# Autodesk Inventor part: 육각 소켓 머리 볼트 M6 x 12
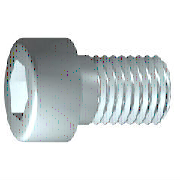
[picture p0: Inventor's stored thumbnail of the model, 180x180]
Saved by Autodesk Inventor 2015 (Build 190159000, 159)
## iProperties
IsCustomPart: 1
Created: 2012-02
Part Number: 육각 소켓 머리 볼트 M6 x 12
Material: 강철, 연강
Description: 원통형 머리 캡 나사
Document SubType Name: Modeling
Standard: JIS B 1176
Designer: mdu-01
Standards Organization: JIS
Language: ko-KR
Size Designation: M6 x 12
Categories: <MemberInstance><Categories><Category DisplayName="조임쇠" InternalName="e4da775c-781d-43d5-af7c-5136215cf5a6" Mnemonic="FSTN"><Category DisplayName="볼트" InternalN
Density: 1 g/cm^3
Appearance: 강철
Author: mdu-01
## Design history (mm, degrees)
sketch "스케치1"
  geometry: L1 (-1.333, 0)-(12, 0); L2 (12, 0)-(12, 3); L3 (12, 3)-(2.5, 3); L4 (2.5, 3)-(1.886, 3); L5 (1.886, 3)-(0, 3); L6 (0, 3)-(0, 5); L7 (0, 5)-(-6, 5); L8 (-6, 5)-(-6, 2.887); L9 (-6, 2.887)-(-3, 2.887); L10 (-3, 2.887)-(-1.333, 0); L11 (-9.6, 0)-(15.6, 0) reference; L12 (0, -1)-(0, 6) reference; L13 (2.5, 3)-(0, 3)
  constraints: 22 end point, 6 parallel, 2 collinear, 2 perpendicular, 1 horizontal, 1 point on line
  dimensions: "d1" = 9.5 distance from line of L3.end L2 (= GEL); "d2" = 0.61355 distance of L4.end L3.end (computed from GAL); "d3" = 6 distance between parallel lines of L8 L6 (= KOH); "d4" = 3 distance of L8.end L9.end (= INTI); "d5" = 60 deg angle of L10 L1; "d6" = 6 diameter of L3 L1 (= GD); "d7" = 6 diameter of L5 L1 (= BDM); "d8" = 5.7735 diameter of L9 L1 (= 1.1547 x SW); "d9" = 10 diameter of L7 L1 (= KOD); "d26" = 12 distance between parallel lines of L12 L2 (= NLG)
revolve "본체" sketch "스케치1" stored, may be unused: angle "d10" = 90 deg
sketch "스케치2"
  geometry: L1 (0, -7)-(0, 7) reference; L2 (-7, 0)-(7, 0) reference; L3 (2.887, 0)-(1.443, -2.5); L4 (1.443, -2.5)-(-1.443, -2.5); L5 (-1.443, -2.5)-(-2.887, 0); L6 (-2.887, 0)-(-1.443, 2.5); L7 (-1.443, 2.5)-(1.443, 2.5); L8 (1.443, 2.5)-(2.887, 0); 2 further points
  constraints: 12 end point, 1 coincident, 1 horizontal alignment, 1 point on line, 12 other
extrude "슬롯" join sketch "스케치2" stored distance "d11" = 10; taper "d12" = 0 deg
workplane "Work Plane1"
fillet "Fillet2" dims "d30" = 0.1 (= R)
body "Solid1"
fillet "모깎기1" dims "d17" = 0.6 (= RR)
feature "스레드" dims "d13" = 9.5 (= GEL), "d14" = 0
chamfer "모따기1" distance "d15" = 0.61345 (= -0.5 x SPD + 0.5 x GD); stored, may be unused: second distance "d16" = 0.61345 (= GUL), angle "d27" = 45 deg
other parameters: "GD" = 6 (= NND) [user parameter; used in 2 equation terms], "NLG" = 12 [user parameter; used in 1 equation term], "GEL" = 9.5 [user parameter; used in 2 equation terms], "KOD" = 10 [user parameter; used in 1 equation term], "KOH" = 6 [user parameter; used in 1 equation term], "INTI" = 3 [user parameter; used in 1 equation term], "GAL" = 0.61345 (= 0.61345 x PTC) [user parameter; used in 1 equation term], "GUL" = 0.61345 (= 0.61345 x PTC) [user parameter; used in 1 equation term], "BDM" = 6 (= NND) [user parameter; used in 1 equation term], "SW" = 5 [user parameter; used in 2 equation terms], "RR" = 0.6 [user parameter; used in 1 equation term], "SPD" = 4.7731 (= NND - 1.2269 x PTC) [user parameter; used in 1 equation term], "d19" = 0, "d28" = 0, "d29" = 0, "R" = 0.1 [user parameter; used in 1 equation term], "PHH" = 0.25 [user parameter], "GD1" = 4.7731 (= THREADDIA - 1.2269 x PTC) [user parameter], "THREADDIA" = 6 [user parameter; used in 1 equation term], "FAWI" = 45 deg [user parameter], "PTC" = 1 [user parameter; used in 5 equation terms], "NND" = 6 [user parameter; used in 3 equation terms], "TOA" = 30 deg [user parameter], "E0" = 5.775 (= 1.155 x SW) [user parameter]
